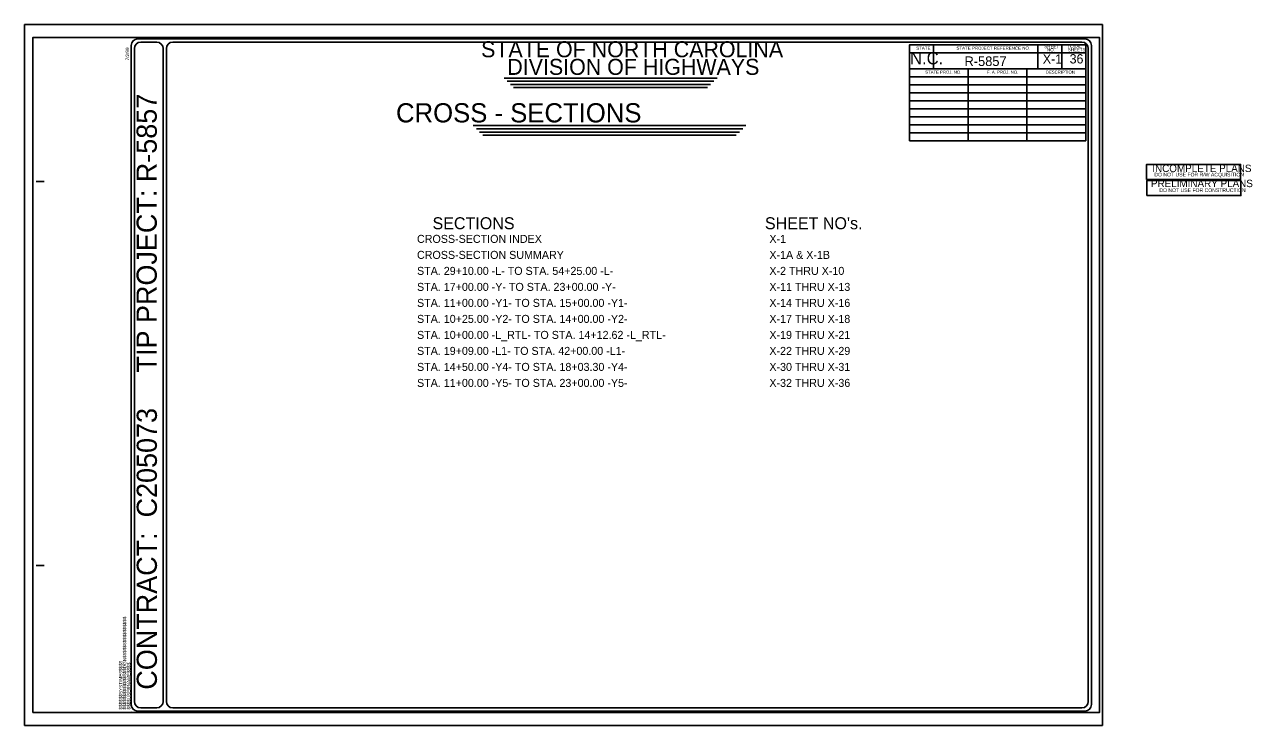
# Model space of a CAD drawing. Extents: x -4 to 187, y -165 to -55.
import ezdxf

# ---------------------------------------------------------------- set-up
doc = ezdxf.new("R2010")
doc.units = 0
for name, color, linetype in [('Old_Level_12', 7, 'Continuous'), ('Old_Level_18', 7, 'Continuous'), ('Old_Level_38', 7, 'Continuous'), ('Old_Level_40', 7, 'Continuous'), ('Old_Level_41', 7, 'Continuous'), ('Old_Level_44', 7, 'Continuous'), ('Sheet Plan CELL', 7, 'Continuous'), ('Sheet Plot Border Inside CELL', 7, 'Continuous'), ('Sheet Plot Border Outside CELL', 7, 'Continuous'), ('Sheet Sticker Incomplete CELL', 7, 'Continuous'), ('Sheet Sticker Preliminary CELL', 7, 'Continuous')]:
    doc.layers.add(name, color=color, linetype=linetype)

msp = doc.modelspace()

# ---------------------------------------------------------------- linework, layer by layer
at = {"layer": 'Old_Level_12'}
for p, q in [((70.58, -63.66), (103.85, -63.66)), ((71.08, -64.16), (103.35, -64.16)), ((71.58, -64.66), (102.85, -64.66)), ((72.08, -65.16), (102.35, -65.16)), ((65.76, -71.09), (108.36, -71.09)), ((66.26, -71.59), (107.86, -71.59)), ((66.76, -72.09), (107.36, -72.09)), ((67.26, -72.59), (106.86, -72.59))]:
    msp.add_line(p, q, dxfattribs=at)
msp.add_lwpolyline([(133.94, -73.45), (161.44, -73.45), (161.44, -72.2), (133.94, -72.2), (133.94, -70.95), (161.44, -70.95), (161.44, -69.7), (133.94, -69.7), (133.94, -68.45), (161.44, -68.45), (161.44, -67.2), (133.94, -67.2), (133.94, -65.95), (161.44, -65.95), (161.44, -64.7), (133.94, -64.7), (133.94, -63.45), (161.44, -63.45), (161.44, -62.2), (133.94, -62.2), (133.94, -59.7), (161.44, -59.7), (161.44, -58.45), (133.94, -58.45), (133.94, -73.45), (143.1, -73.45), (143.1, -62.2), (137.69, -62.2), (137.69, -58.45), (153.94, -58.45), (153.94, -62.2), (152.27, -62.2), (152.27, -73.45), (161.44, -73.45), (161.44, -58.45), (157.69, -58.45), (157.69, -62.2)], dxfattribs=at)
at = {"layer": 'Old_Level_18'}
for p, q in [((17.34, -161.05), (17.34, -59.05)), ((17.84, -161.05), (17.84, -59.05)), ((12.34, -162.55), (12.34, -162.55)), ((12.34, -162.55), (12.34, -162.55)), ((12.34, -162.55), (12.34, -162.55))]:
    msp.add_line(p, q, dxfattribs=at)
for points in [[(12.34, -58.55), (12.34, -161.55)], [(12.34, -58.55), (12.34, -161.55)], [(12.84, -59.05), (12.84, -161.05)], [(161.34, -57.55), (13.34, -57.55)], [(16.34, -58.05), (13.84, -58.05)], [(160.84, -58.05), (18.84, -58.05)], [(161.84, -161.05), (161.84, -59.05)], [(162.34, -161.55), (162.34, -58.55)], [(13.34, -162.55), (161.34, -162.55)], [(13.84, -162.05), (16.34, -162.05)], [(18.84, -162.05), (160.84, -162.05)]]:
    msp.add_lwpolyline(points, dxfattribs=at)
for centre, start, end in [((13.34, -58.55), 90, 180), ((13.84, -59.05), 90, 180), ((16.34, -59.05), 0, 90), ((18.84, -59.05), 90, 180), ((160.84, -59.05), 0, 90), ((161.34, -58.55), 0, 90), ((13.84, -161.05), 180, 270), ((16.34, -161.05), 270, 360), ((18.84, -161.05), 180, 270), ((160.84, -161.05), 270, 360), ((13.34, -161.55), 180, 270), ((161.34, -161.55), 270, 360)]:
    msp.add_arc(centre, 1, start, end, dxfattribs=at)
at = {"layer": 'Old_Level_38'}
msp.add_line((12.34, -162.55), (12.34, -162.55), dxfattribs=at)
at = {"layer": 'Old_Level_40'}
msp.add_line((12.34, -162.55), (12.34, -162.55), dxfattribs=at)
msp.add_line((12.34, -162.55), (12.34, -162.55), dxfattribs=at)
msp.add_line((12.34, -162.55), (12.34, -162.55), dxfattribs=at)
msp.add_line((12.34, -162.55), (12.34, -162.55), dxfattribs=at)
at = {"layer": 'Old_Level_41'}
for p, q in [((-2.51, -79.8), (-1.26, -79.8)), ((-2.51, -79.8), (-1.26, -79.8)), ((-2.51, -139.8), (-1.26, -139.8)), ((-2.51, -139.8), (-1.26, -139.8))]:
    msp.add_line(p, q, dxfattribs=at)
at = {"layer": 'Sheet Plan CELL'}
for p, q in [((-2.51, -79.8), (-1.26, -79.8)), ((-2.51, -139.8), (-1.26, -139.8)), ((12.34, -162.55), (12.34, -162.55))]:
    msp.add_line(p, q, dxfattribs=at)
at = {"layer": 'Sheet Plot Border Inside CELL'}
msp.add_lwpolyline([(-3.01, -162.8), (163.59, -162.8), (163.59, -57.3), (-3.01, -57.3)], close=True, dxfattribs=at)
at = {"layer": 'Sheet Plot Border Outside CELL'}
msp.add_lwpolyline([(-4.31, -164.8), (164.04, -164.8), (164.04, -55.3), (-4.31, -55.3)], close=True, dxfattribs=at)
at = {"layer": 'Sheet Sticker Incomplete CELL'}
msp.add_lwpolyline([(170.94, -79.51), (170.94, -77.16), (185.64, -77.16), (185.64, -79.51)], close=True, dxfattribs=at)
at = {"layer": 'Sheet Sticker Preliminary CELL'}
msp.add_lwpolyline([(170.98, -82.02), (170.98, -79.67), (185.68, -79.67), (185.68, -82.02)], close=True, dxfattribs=at)

# ---------------------------------------------------------------- texts
at = {"layer": 'Old_Level_18'}
for s, p in [('TIP PROJECT: R-5857', (16.34, -109.65)), ('CONTRACT:  C205073', (16.36, -159.21))]:
    msp.add_text(s, height=3.15, rotation=90, dxfattribs=at).set_placement(p)
at = {"layer": 'Old_Level_38'}
for s, height, p in [('R-5857', 1.5, (142.51, -61.78)), ('       CROSS - SECTIONS      ', 3, (45.91, -70.59))]:
    msp.add_text(s, height=height, dxfattribs=at).set_placement(p)
at = {"layer": 'Old_Level_41'}
for s, p in [('$$$$$$$$$$$$$$$$DGN$$$$$$$$$$$$$$$$', (11.57, -162.31)), ('$$$$$$SYSTIME$$$$$', (10.97, -162.31)), ('$$$$USERNAME$$$$', (12.23, -162.31))]:
    msp.add_text(s, height=0.525, rotation=90, dxfattribs=at).set_placement(p)
at = {"layer": 'Old_Level_44'}
for s, height, p in [('STATE OF NORTH CAROLINA', 2.5, (67, -60.41)), ('STATE', 0.5, (134.96, -59.23)), ('STATE PROJECT REFERENCE NO.', 0.5, (141.25, -59.23)), ('SHEET', 0.5, (154.98, -59)), ('NO.', 0.5, (155.4, -59.5)), ('TOTAL', 0.5, (158.6, -58.97)), ('SHEETS', 0.5, (158.64, -59.47)), ('DIVISION OF HIGHWAYS', 2.5, (71.09, -63.16)), ('N.C.', 1.935, (134.01, -61.52)), ('X-1', 1.451, (154.74, -61.4)), ('36', 1.451, (158.93, -61.38)), ('STATE PROJ. NO.', 0.48, (136.38, -62.97)), ('F. A. PROJ. NO.', 0.48, (146.01, -62.97)), ('DESCRIPTION', 0.48, (155.22, -62.97)), ('SECTIONS', 1.875, (59.41, -87.28)), ("SHEET NO's.", 1.875, (111.33, -87.28)), ('CROSS-SECTION INDEX', 1.25, (56.99, -89.41)), ('X-1', 1.25, (112.03, -89.41)), ('CROSS-SECTION SUMMARY', 1.25, (56.99, -91.91)), ('X-1A & X-1B', 1.25, (112.03, -91.91)), ('STA. 29+10.00 -L- TO STA. 54+25.00 -L-', 1.25, (56.99, -94.41)), ('X-2 THRU X-10', 1.25, (112.03, -94.41)), ('STA. 17+00.00 -Y- TO STA. 23+00.00 -Y-', 1.25, (56.99, -96.91)), ('X-11 THRU X-13', 1.25, (112.03, -96.91)), ('STA. 11+00.00 -Y1- TO STA. 15+00.00 -Y1-', 1.25, (56.99, -99.41)), ('X-14 THRU X-16', 1.25, (112.03, -99.41)), ('STA. 10+25.00 -Y2- TO STA. 14+00.00 -Y2-', 1.25, (56.99, -101.91)), ('X-17 THRU X-18', 1.25, (112.03, -101.91)), ('STA. 10+00.00 -L_RTL- TO STA. 14+12.62 -L_RTL-', 1.25, (56.99, -104.41)), ('X-19 THRU X-21', 1.25, (112.03, -104.41)), ('STA. 19+09.00 -L1- TO STA. 42+00.00 -L1-', 1.25, (56.99, -106.91)), ('X-22 THRU X-29', 1.25, (112.03, -106.91)), ('STA. 14+50.00 -Y4- TO STA. 18+03.30 -Y4-', 1.25, (56.99, -109.41)), ('X-30 THRU X-31', 1.25, (112.03, -109.41)), ('STA. 11+00.00 -Y5- TO STA. 23+00.00 -Y5-', 1.25, (56.99, -111.91)), ('X-32 THRU X-36', 1.25, (112.03, -111.91))]:
    msp.add_text(s, height=height, dxfattribs=at).set_placement(p)
at = {"layer": 'Sheet Plan CELL'}
msp.add_text('7/2/99', height=0.525, rotation=90, dxfattribs=at).set_placement((12.01, -60.9))
at = {"layer": 'Sheet Sticker Incomplete CELL'}
for s, height, p in [('INCOMPLETE PLANS', 1.152, (171.84, -78.34)), ('DO NOT USE FOR R/W ACQUISITION', 0.576, (172.16, -79.03))]:
    msp.add_text(s, height=height, dxfattribs=at).set_placement(p)
at = {"layer": 'Sheet Sticker Preliminary CELL'}
for s, height, p in [('PRELIMINARY PLANS', 1.152, (171.63, -80.7)), ('DO NOT USE FOR CONSTRUCTION', 0.576, (172.94, -81.47))]:
    msp.add_text(s, height=height, dxfattribs=at).set_placement(p)

doc.saveas('drawing.dxf')
